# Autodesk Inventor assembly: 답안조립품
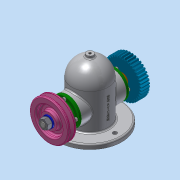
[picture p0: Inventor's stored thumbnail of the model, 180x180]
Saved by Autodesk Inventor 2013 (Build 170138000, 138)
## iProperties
Created: 2019-11
Part Number: 답안조립품
Document SubType Name: Assembly
Designer: Administrator
Author: Administrator
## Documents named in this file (14)
- C:\Users\Administrator\Desktop\답안조립품.iam
- C:\Users\Administrator\Desktop\본체.ipt
- C:\Users\Administrator\Desktop\공용부품\V-벨트풀리.ipt
- V-벨트풀리.ipt
- C:\Users\Administrator\Desktop\공용부품\너트 M12x1.25.ipt
- C:\Users\Administrator\Desktop\공용부품\베어링 6203.ipt
- C:\Users\Administrator\Desktop\공용부품\볼트 M4.ipt
- C:\Users\Administrator\Desktop\공용부품\부시.ipt
- C:\Users\Administrator\Desktop\공용부품\스퍼기어.ipt
- C:\Users\Administrator\Desktop\공용부품\오일 실 26 38 8.ipt
- C:\Users\Administrator\Desktop\공용부품\와셔 12x24.ipt
- C:\Users\Administrator\Desktop\공용부품\축.ipt
- C:\Users\Administrator\Desktop\공용부품\커버.ipt
- C:\Users\Administrator\Desktop\공용부품\키 5x5x12.ipt
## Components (1 placed, 1 different names)
1. V-벨트풀리:1
